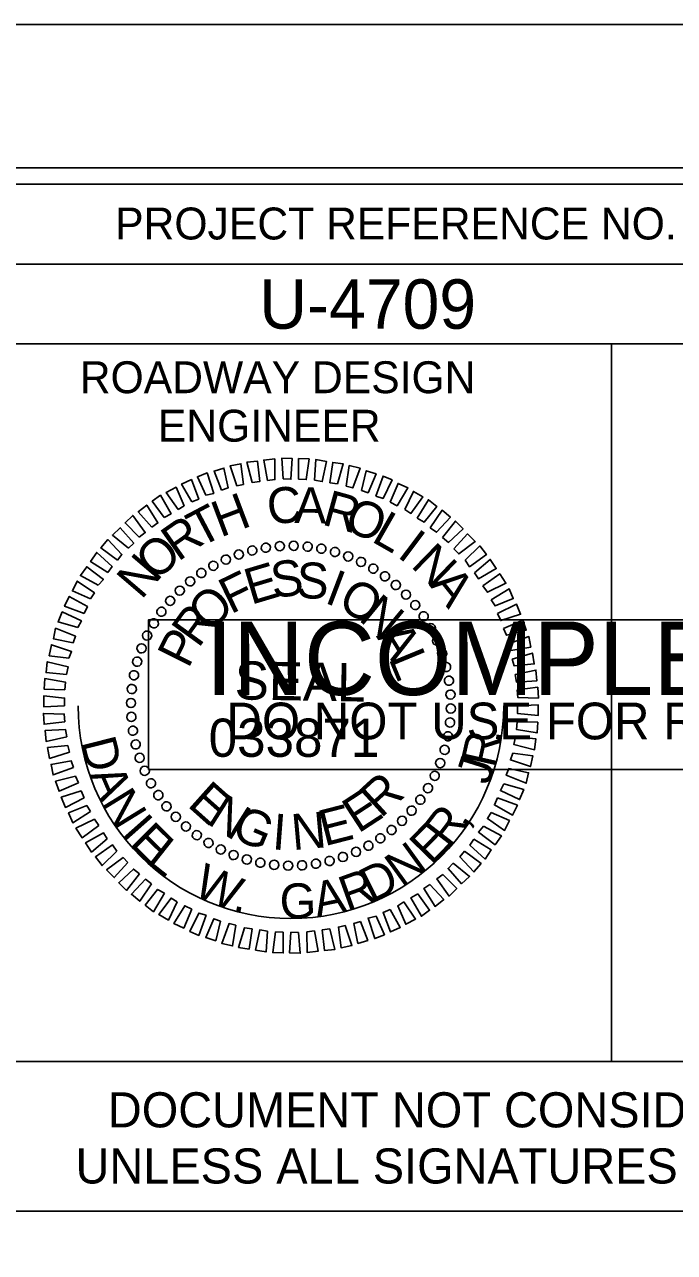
# Model space of a CAD drawing. Extents: x 1779926 to 1781626, y 618464 to 619564.
# Drawn here: x 1781400.9 to 1781502.8, y 619371.7 to 619564.2 of the extents above; entities that cross this region are included whole.
import ezdxf

# ---------------------------------------------------------------- set-up
doc = ezdxf.new("R2010")
doc.units = 0
for name, color, linetype in [('Old_Level_58', 7, 'Continuous'), ('Scratch_Level_0', 7, 'Continuous'), ('Sheet Data Field CELL', 7, 'Continuous'), ('Sheet Plot Border Inside CELL', 7, 'Continuous'), ('Sheet Plot Border Outside CELL', 7, 'Continuous'), ('Sheet Professional Seal CELL', 7, 'Continuous'), ('Sheet Profile CELL', 7, 'Continuous'), ('Sheet Profile Grid Major CELL', 7, 'Continuous'), ('Sheet Profile Grid Minor CELL', 7, 'Continuous'), ('Sheet Sticker Exception Certification CELL', 7, 'Continuous'), ('Sheet Sticker Incomplete CELL', 7, 'Continuous')]:
    doc.layers.add(name, color=color, linetype=linetype)

msp = doc.modelspace()

# ---------------------------------------------------------------- linework, layer by layer
at = {"layer": 'Old_Level_58'}
msp.add_lwpolyline([(1781392.9, 619378.14), (1781592.95, 619378.14), (1781592.95, 619314.19), (1781392.9, 619314.19)], close=True, dxfattribs=at)
at = {"layer": 'Scratch_Level_0'}
msp.add_arc((1781442.68, 619457.4), 33.36, 180, 360, dxfattribs=at)
at = {"layer": 'Sheet Plot Border Inside CELL'}
msp.add_lwpolyline([(1779938.96, 618486.64), (1781605.46, 618486.64), (1781605.46, 619541.74), (1779938.96, 619541.74)], close=True, dxfattribs=at)
at = {"layer": 'Sheet Plot Border Outside CELL'}
msp.add_lwpolyline([(1779925.96, 618464.19), (1781625.96, 618464.19), (1781625.96, 619564.19), (1779925.96, 619564.19)], close=True, dxfattribs=at)
at = {"layer": 'Sheet Professional Seal CELL'}
for p, q in [((1781440.93, 619482.45), (1781440.93, 619482.45)), ((1781443.13, 619482.5), (1781443.13, 619482.5)), ((1781445.33, 619482.35), (1781445.33, 619482.35)), ((1781434.48, 619481.15), (1781434.48, 619481.15)), ((1781436.58, 619481.75), (1781436.58, 619481.75)), ((1781438.78, 619482.15), (1781438.78, 619482.15)), ((1781447.48, 619482), (1781447.48, 619482)), ((1781449.58, 619481.55), (1781449.58, 619481.55)), ((1781451.68, 619480.85), (1781451.68, 619480.85)), ((1781430.53, 619479.35), (1781430.53, 619479.35)), ((1781432.48, 619480.35), (1781432.48, 619480.35)), ((1781453.68, 619479.95), (1781453.68, 619479.95)), ((1781455.63, 619478.95), (1781455.63, 619478.95)), ((1781426.88, 619476.95), (1781426.88, 619476.95)), ((1781428.63, 619478.2), (1781428.63, 619478.2)), ((1781457.43, 619477.7), (1781457.43, 619477.7)), ((1781425.23, 619475.45), (1781425.23, 619475.45)), ((1781459.18, 619476.35), (1781459.18, 619476.35)), ((1781460.73, 619474.85), (1781460.73, 619474.85)), ((1781423.73, 619473.9), (1781423.73, 619473.9)), ((1781462.23, 619473.2), (1781462.23, 619473.2)), ((1781422.38, 619472.15), (1781422.38, 619472.15)), ((1781463.48, 619471.45), (1781463.48, 619471.45)), ((1781421.13, 619470.35), (1781421.13, 619470.35)), ((1781464.63, 619469.55), (1781464.63, 619469.55)), ((1781420.13, 619468.4), (1781420.13, 619468.4)), ((1781465.63, 619467.6), (1781465.63, 619467.6)), ((1781419.23, 619466.4), (1781419.23, 619466.4)), ((1781466.43, 619465.6), (1781466.43, 619465.6)), ((1781418.53, 619464.3), (1781418.53, 619464.3)), ((1781467.03, 619463.5), (1781467.03, 619463.5)), ((1781418.08, 619462.2), (1781418.08, 619462.2)), ((1781467.43, 619461.3), (1781467.43, 619461.3)), ((1781417.73, 619460.05), (1781417.73, 619460.05)), ((1781417.58, 619457.85), (1781417.58, 619457.85)), ((1781442.68, 619457.4), (1781442.68, 619457.4)), ((1781467.73, 619459.15), (1781467.73, 619459.15)), ((1781417.63, 619455.65), (1781417.63, 619455.65)), ((1781467.78, 619456.95), (1781467.78, 619456.95)), ((1781417.93, 619453.5), (1781417.93, 619453.5)), ((1781467.63, 619454.75), (1781467.63, 619454.75)), ((1781467.28, 619452.6), (1781467.28, 619452.6)), ((1781418.33, 619451.3), (1781418.33, 619451.3)), ((1781466.83, 619450.5), (1781466.83, 619450.5)), ((1781418.93, 619449.2), (1781418.93, 619449.2)), ((1781466.13, 619448.4), (1781466.13, 619448.4)), ((1781419.73, 619447.2), (1781419.73, 619447.2)), ((1781465.23, 619446.4), (1781465.23, 619446.4)), ((1781420.73, 619445.25), (1781420.73, 619445.25)), ((1781464.23, 619444.45), (1781464.23, 619444.45)), ((1781421.88, 619443.35), (1781421.88, 619443.35)), ((1781462.98, 619442.65), (1781462.98, 619442.65)), ((1781423.13, 619441.6), (1781423.13, 619441.6)), ((1781461.63, 619440.9), (1781461.63, 619440.9)), ((1781424.63, 619439.95), (1781424.63, 619439.95)), ((1781426.18, 619438.45), (1781426.18, 619438.45)), ((1781460.13, 619439.35), (1781460.13, 619439.35)), ((1781427.93, 619437.1), (1781427.93, 619437.1)), ((1781456.73, 619436.6), (1781456.73, 619436.6)), ((1781458.48, 619437.85), (1781458.48, 619437.85)), ((1781429.73, 619435.85), (1781429.73, 619435.85)), ((1781431.68, 619434.85), (1781431.68, 619434.85)), ((1781452.88, 619434.45), (1781452.88, 619434.45)), ((1781454.83, 619435.45), (1781454.83, 619435.45)), ((1781433.68, 619433.95), (1781433.68, 619433.95)), ((1781435.78, 619433.25), (1781435.78, 619433.25)), ((1781437.88, 619432.8), (1781437.88, 619432.8)), ((1781440.03, 619432.45), (1781440.03, 619432.45)), ((1781442.23, 619432.3), (1781442.23, 619432.3)), ((1781444.43, 619432.35), (1781444.43, 619432.35)), ((1781446.58, 619432.65), (1781446.58, 619432.65)), ((1781448.78, 619433.05), (1781448.78, 619433.05)), ((1781450.88, 619433.65), (1781450.88, 619433.65))]:
    msp.add_line(p, q, dxfattribs=at)
for points in [[(1781438.98, 619492.7), (1781438.43, 619495.9), (1781440.13, 619496.1), (1781440.18, 619492.85)], [(1781441.48, 619492.95), (1781441.23, 619496.2), (1781442.88, 619496.15), (1781442.68, 619492.9)], [(1781443.88, 619492.9), (1781443.88, 619496.15), (1781445.53, 619496.1), (1781445.08, 619492.85)], [(1781446.38, 619492.75), (1781446.58, 619496), (1781448.23, 619495.7), (1781447.58, 619492.55)], [(1781429.33, 619490.4), (1781428.03, 619493.3), (1781429.53, 619493.9), (1781430.58, 619490.7)], [(1781431.78, 619491.2), (1781430.63, 619494.2), (1781432.18, 619494.65), (1781432.83, 619491.55)], [(1781434.18, 619491.85), (1781433.13, 619495), (1781434.83, 619495.35), (1781435.23, 619492.1)], [(1781436.58, 619492.4), (1781435.78, 619495.6), (1781437.43, 619495.75), (1781437.78, 619492.55)], [(1781448.78, 619492.35), (1781449.23, 619495.55), (1781450.88, 619495.3), (1781449.98, 619492.2)], [(1781451.33, 619491.8), (1781451.83, 619495.05), (1781453.53, 619494.65), (1781452.38, 619491.55)], [(1781453.73, 619491.15), (1781454.48, 619494.25), (1781456.03, 619493.75), (1781454.78, 619490.8)], [(1781427.13, 619489.35), (1781425.53, 619492.15), (1781427.08, 619492.85), (1781428.23, 619489.8)], [(1781455.98, 619490.25), (1781457.13, 619493.4), (1781458.53, 619492.8), (1781457.13, 619489.9)], [(1781458.23, 619489.3), (1781459.48, 619492.25), (1781461.03, 619491.55), (1781459.33, 619488.75)], [(1781422.78, 619486.9), (1781420.93, 619489.45), (1781422.23, 619490.4), (1781423.88, 619487.5)], [(1781424.98, 619488.15), (1781423.13, 619490.85), (1781424.68, 619491.65), (1781425.93, 619488.75)], [(1781460.53, 619488.15), (1781461.88, 619491), (1781463.38, 619490.15), (1781461.48, 619487.55)], [(1781420.88, 619485.4), (1781418.73, 619487.8), (1781420.08, 619488.85), (1781421.83, 619486.05)], [(1781462.48, 619486.8), (1781464.23, 619489.7), (1781465.53, 619488.65), (1781463.58, 619486.2)], [(1781418.88, 619483.85), (1781416.68, 619486.05), (1781417.88, 619487.25), (1781419.83, 619484.55)], [(1781464.53, 619485.3), (1781466.38, 619488.05), (1781467.68, 619486.95), (1781465.48, 619484.6)], [(1781466.43, 619483.75), (1781468.48, 619486.35), (1781469.68, 619485.15), (1781467.38, 619483)], [(1781417.23, 619482.1), (1781414.68, 619484.15), (1781415.93, 619485.3), (1781418.03, 619482.9)], [(1781468.23, 619482), (1781470.38, 619484.35), (1781471.58, 619483.15), (1781468.98, 619481.2)], [(1781415.48, 619480.2), (1781412.88, 619482.15), (1781413.98, 619483.45), (1781416.18, 619481.1)], [(1781469.98, 619480.2), (1781472.28, 619482.45), (1781473.33, 619481.1), (1781470.68, 619479.2)], [(1781413.98, 619478.3), (1781411.28, 619480), (1781412.23, 619481.45), (1781414.63, 619479.25)], [(1781412.48, 619476.3), (1781409.68, 619477.8), (1781410.68, 619479.2), (1781413.28, 619477.2)], [(1781471.48, 619478.25), (1781473.93, 619480.35), (1781474.88, 619478.9), (1781472.08, 619477.3)], [(1781411.28, 619474.15), (1781408.43, 619475.4), (1781409.18, 619476.95), (1781411.88, 619475.1)], [(1781472.78, 619476.2), (1781475.43, 619478.1), (1781476.38, 619476.6), (1781473.48, 619475.2)], [(1781474.08, 619474), (1781476.88, 619475.75), (1781477.53, 619474.2), (1781474.68, 619473.05)], [(1781410.28, 619471.85), (1781407.18, 619473), (1781407.93, 619474.55), (1781410.78, 619472.95)], [(1781475.08, 619471.85), (1781478.03, 619473.35), (1781478.68, 619471.75), (1781475.58, 619470.75)], [(1781409.28, 619469.65), (1781406.18, 619470.55), (1781406.83, 619472.1), (1781409.83, 619470.7)], [(1781475.98, 619469.5), (1781479.03, 619470.8), (1781479.58, 619469.25), (1781476.48, 619468.45)], [(1781408.53, 619467.25), (1781405.43, 619467.9), (1781405.78, 619469.55), (1781408.93, 619468.3)], [(1781407.88, 619464.85), (1781404.78, 619465.25), (1781405.13, 619466.95), (1781408.28, 619465.9)], [(1781476.78, 619467.1), (1781479.98, 619468.25), (1781480.28, 619466.6), (1781477.13, 619466.05)], [(1781477.38, 619464.7), (1781480.53, 619465.65), (1781480.83, 619463.95), (1781477.68, 619463.65)], [(1781407.48, 619462.3), (1781404.28, 619462.6), (1781404.48, 619464.3), (1781407.73, 619463.5)], [(1781407.23, 619459.9), (1781403.98, 619460), (1781404.08, 619461.65), (1781407.33, 619461.1)], [(1781477.83, 619462.3), (1781481.08, 619463), (1781481.23, 619461.3), (1781478.03, 619461.1)], [(1781478.13, 619459.9), (1781481.38, 619460.3), (1781481.48, 619458.6), (1781478.23, 619458.7)], [(1781407.18, 619457.4), (1781403.93, 619457.25), (1781403.93, 619458.95), (1781407.18, 619458.6)], [(1781478.18, 619457.4), (1781481.43, 619457.55), (1781481.43, 619455.85), (1781478.18, 619456.2)], [(1781407.23, 619454.9), (1781403.98, 619454.5), (1781403.88, 619456.2), (1781407.13, 619456.1)], [(1781407.53, 619452.5), (1781404.28, 619451.8), (1781404.13, 619453.5), (1781407.33, 619453.7)], [(1781478.13, 619454.9), (1781481.38, 619454.8), (1781481.28, 619453.15), (1781478.03, 619453.7)], [(1781477.88, 619452.5), (1781481.08, 619452.2), (1781480.88, 619450.5), (1781477.63, 619451.3)], [(1781407.98, 619450.1), (1781404.83, 619449.15), (1781404.53, 619450.85), (1781407.68, 619451.15)], [(1781477.48, 619449.95), (1781480.58, 619449.55), (1781480.23, 619447.85), (1781477.08, 619448.9)], [(1781408.58, 619447.7), (1781405.38, 619446.55), (1781405.08, 619448.2), (1781408.23, 619448.75)], [(1781409.38, 619445.3), (1781406.33, 619444), (1781405.78, 619445.55), (1781408.88, 619446.35)], [(1781476.83, 619447.55), (1781479.93, 619446.9), (1781479.58, 619445.25), (1781476.43, 619446.5)], [(1781410.28, 619442.95), (1781407.33, 619441.45), (1781406.68, 619443.05), (1781409.78, 619444.05)], [(1781476.08, 619445.15), (1781479.18, 619444.25), (1781478.53, 619442.7), (1781475.53, 619444.1)], [(1781475.08, 619442.95), (1781478.18, 619441.8), (1781477.43, 619440.25), (1781474.58, 619441.85)], [(1781411.28, 619440.8), (1781408.48, 619439.05), (1781407.83, 619440.6), (1781410.68, 619441.75)], [(1781474.08, 619440.65), (1781476.93, 619439.4), (1781476.18, 619437.85), (1781473.48, 619439.7)], [(1781412.58, 619438.6), (1781409.93, 619436.7), (1781408.98, 619438.2), (1781411.88, 619439.6)], [(1781472.88, 619438.5), (1781475.68, 619437), (1781474.68, 619435.6), (1781472.08, 619437.6)], [(1781413.88, 619436.55), (1781411.43, 619434.45), (1781410.48, 619435.9), (1781413.28, 619437.5)], [(1781471.38, 619436.5), (1781474.08, 619434.8), (1781473.13, 619433.35), (1781470.73, 619435.55)], [(1781415.38, 619434.6), (1781413.08, 619432.35), (1781412.03, 619433.7), (1781414.68, 619435.6)], [(1781469.88, 619434.6), (1781472.48, 619432.65), (1781471.38, 619431.35), (1781469.18, 619433.7)], [(1781417.13, 619432.8), (1781414.98, 619430.45), (1781413.78, 619431.65), (1781416.38, 619433.6)], [(1781468.13, 619432.7), (1781470.68, 619430.65), (1781469.43, 619429.5), (1781467.33, 619431.9)], [(1781418.93, 619431.05), (1781416.88, 619428.45), (1781415.68, 619429.65), (1781417.98, 619431.8)], [(1781466.48, 619430.95), (1781468.68, 619428.75), (1781467.48, 619427.55), (1781465.53, 619430.25)], [(1781420.83, 619429.5), (1781418.98, 619426.75), (1781417.68, 619427.85), (1781419.88, 619430.2)], [(1781422.88, 619428), (1781421.13, 619425.1), (1781419.83, 619426.15), (1781421.78, 619428.6)], [(1781464.48, 619429.4), (1781466.63, 619427), (1781465.28, 619425.95), (1781463.53, 619428.75)], [(1781424.83, 619426.65), (1781423.48, 619423.8), (1781421.98, 619424.65), (1781423.88, 619427.25)], [(1781460.38, 619426.65), (1781462.23, 619423.95), (1781460.68, 619423.15), (1781459.43, 619426.05)], [(1781462.58, 619427.9), (1781464.43, 619425.35), (1781463.13, 619424.4), (1781461.48, 619427.3)], [(1781427.13, 619425.5), (1781425.88, 619422.55), (1781424.33, 619423.25), (1781426.03, 619426.05)], [(1781429.38, 619424.55), (1781428.23, 619421.4), (1781426.83, 619422), (1781428.23, 619424.9)], [(1781458.23, 619425.45), (1781459.83, 619422.65), (1781458.28, 619421.95), (1781457.13, 619425)], [(1781431.63, 619423.65), (1781430.88, 619420.55), (1781429.33, 619421.05), (1781430.58, 619424)], [(1781434.03, 619423), (1781433.53, 619419.75), (1781431.83, 619420.15), (1781432.98, 619423.25)], [(1781451.18, 619422.95), (1781452.23, 619419.8), (1781450.53, 619419.45), (1781450.13, 619422.7)], [(1781453.58, 619423.6), (1781454.73, 619420.6), (1781453.18, 619420.15), (1781452.53, 619423.25)], [(1781456.03, 619424.4), (1781457.33, 619421.5), (1781455.83, 619420.9), (1781454.78, 619424.1)], [(1781436.58, 619422.45), (1781436.13, 619419.25), (1781434.48, 619419.5), (1781435.38, 619422.6)], [(1781438.98, 619422.05), (1781438.78, 619418.8), (1781437.13, 619419.1), (1781437.78, 619422.25)], [(1781441.48, 619421.9), (1781441.48, 619418.65), (1781439.83, 619418.7), (1781440.28, 619421.95)], [(1781443.88, 619421.85), (1781444.13, 619418.6), (1781442.48, 619418.65), (1781442.68, 619421.9)], [(1781446.38, 619422.1), (1781446.93, 619418.9), (1781445.23, 619418.7), (1781445.18, 619421.95)], [(1781448.78, 619422.4), (1781449.58, 619419.2), (1781447.93, 619419.05), (1781447.58, 619422.25)]]:
    msp.add_lwpolyline(points, close=True, dxfattribs=at)
for centre, major_axis in [((1781436.61, 619481.74), (-0.174, 0.699)), ((1781438.75, 619482.17), (-0.113, 0.711)), ((1781440.93, 619482.42), (-0.05, 0.718)), ((1781443.11, 619482.48), (0.013, 0.72)), ((1781445.3, 619482.34), (0.075, 0.716)), ((1781447.46, 619482.02), (0.137, 0.707)), ((1781432.47, 619480.31), (-0.293, 0.658)), ((1781434.51, 619481.11), (-0.234, 0.681)), ((1781449.59, 619481.51), (0.198, 0.692)), ((1781451.66, 619480.81), (0.258, 0.672)), ((1781453.67, 619479.94), (0.316, 0.647)), ((1781428.65, 619478.19), (-0.403, 0.597)), ((1781430.52, 619479.34), (-0.349, 0.63)), ((1781455.59, 619478.9), (0.371, 0.617)), ((1781457.42, 619477.69), (0.423, 0.582)), ((1781426.89, 619476.89), (-0.453, 0.56)), ((1781459.13, 619476.33), (0.472, 0.543)), ((1781423.75, 619473.85), (-0.543, 0.472)), ((1781425.25, 619475.44), (-0.5, 0.518)), ((1781460.72, 619474.82), (0.518, 0.5)), ((1781422.38, 619472.14), (-0.582, 0.423)), ((1781462.17, 619473.18), (0.56, 0.453)), ((1781421.18, 619470.32), (-0.617, 0.371)), ((1781463.47, 619471.42), (0.597, 0.403)), ((1781420.13, 619468.39), (-0.647, 0.316)), ((1781464.61, 619469.56), (0.63, 0.349)), ((1781419.26, 619466.39), (-0.672, 0.258)), ((1781465.59, 619467.6), (0.658, 0.293)), ((1781418.57, 619464.31), (-0.692, 0.198)), ((1781466.39, 619465.57), (0.681, 0.234)), ((1781467.01, 619463.47), (0.699, 0.174)), ((1781418.06, 619462.19), (-0.707, 0.137)), ((1781467.45, 619461.32), (0.711, 0.113)), ((1781417.73, 619460.02), (-0.716, 0.075)), ((1781467.69, 619459.15), (0.718, 0.05)), ((1781417.6, 619457.84), (-0.72, 0.013)), ((1781467.75, 619456.96), (0.72, -0.013)), ((1781417.66, 619455.65), (-0.718, -0.05)), ((1781467.62, 619454.78), (0.716, -0.075)), ((1781417.9, 619453.48), (-0.711, -0.113)), ((1781418.34, 619451.33), (-0.699, -0.174)), ((1781467.29, 619452.61), (0.707, -0.137)), ((1781418.96, 619449.24), (-0.681, -0.234)), ((1781466.78, 619450.49), (0.692, -0.198)), ((1781419.76, 619447.2), (-0.658, -0.293)), ((1781466.09, 619448.41), (0.672, -0.258)), ((1781420.74, 619445.24), (-0.63, -0.349)), ((1781465.22, 619446.41), (0.647, -0.316)), ((1781421.88, 619443.38), (-0.597, -0.403)), ((1781464.17, 619444.48), (0.617, -0.371)), ((1781423.18, 619441.62), (-0.56, -0.453)), ((1781462.97, 619442.66), (0.582, -0.423)), ((1781424.63, 619439.98), (-0.518, -0.5)), ((1781460.1, 619439.36), (0.5, -0.518)), ((1781461.6, 619440.95), (0.543, -0.472)), ((1781426.22, 619438.47), (-0.472, -0.543)), ((1781458.46, 619437.91), (0.453, -0.56)), ((1781427.93, 619437.11), (-0.423, -0.582)), ((1781429.76, 619435.9), (-0.371, -0.617)), ((1781454.83, 619435.46), (0.349, -0.63)), ((1781456.7, 619436.61), (0.403, -0.597)), ((1781431.68, 619434.86), (-0.316, -0.647)), ((1781433.69, 619433.99), (-0.258, -0.672)), ((1781450.84, 619433.69), (0.234, -0.681)), ((1781452.88, 619434.49), (0.293, -0.658)), ((1781435.76, 619433.29), (-0.198, -0.692)), ((1781437.89, 619432.78), (-0.137, -0.707)), ((1781440.05, 619432.46), (-0.075, -0.716)), ((1781442.24, 619432.32), (-0.013, -0.72)), ((1781444.42, 619432.38), (0.05, -0.718)), ((1781446.6, 619432.63), (0.113, -0.711)), ((1781448.74, 619433.07), (0.174, -0.699))]:
    msp.add_ellipse(centre, major_axis=major_axis, ratio=0.999708, dxfattribs=at)
at = {"layer": 'Sheet Profile CELL'}
for p, q in [((1781392.91, 619526.64), (1781592.96, 619526.64)), ((1781492.96, 619514.14), (1781492.96, 619401.69))]:
    msp.add_line(p, q, dxfattribs=at)
for points in [[(1781592.96, 619539.19), (1780092.96, 619539.19), (1780092.96, 618489.19), (1781592.96, 618489.19)], [(1781392.91, 619539.19), (1781592.96, 619539.19), (1781592.96, 619514.14), (1781392.91, 619514.14)], [(1781392.91, 619514.14), (1781492.96, 619514.14), (1781492.96, 619401.64), (1781392.91, 619401.64)], [(1781492.96, 619514.14), (1781592.96, 619514.14), (1781592.96, 619401.64), (1781492.96, 619401.64)]]:
    msp.add_lwpolyline(points, close=True, dxfattribs=at)
at = {"layer": 'Sheet Profile Grid Major CELL'}
msp.add_lwpolyline([(1780842.96, 619039.19), (1780892.96, 619039.19), (1780892.96, 619539.19), (1780942.96, 619539.19), (1780942.96, 619039.19), (1780992.96, 619039.19), (1780992.96, 619539.19), (1781042.96, 619539.19), (1781042.96, 619039.19), (1781092.96, 619039.19), (1781092.96, 619539.19), (1781142.96, 619539.19), (1781142.96, 619039.19), (1781192.96, 619039.19), (1781192.96, 619539.19), (1781242.96, 619539.19), (1781242.96, 619039.19), (1781292.96, 619039.19), (1781292.96, 619539.19), (1781342.96, 619539.19), (1781342.96, 619039.19), (1781392.96, 619039.19), (1781392.96, 619539.19), (1781419.26, 619539.19)], dxfattribs=at)
at = {"layer": 'Sheet Sticker Exception Certification CELL'}
for p, q in [((1781392.91, 619401.64), (1781592.95, 619401.64)), ((1781392.91, 619401.64), (1781592.95, 619401.64)), ((1781592.95, 619378.14), (1781392.91, 619378.14)), ((1781592.95, 619378.14), (1781392.91, 619378.14))]:
    msp.add_line(p, q, dxfattribs=at)
at = {"layer": 'Sheet Sticker Incomplete CELL'}
msp.add_lwpolyline([(1781420.37, 619447.38), (1781420.37, 619470.88), (1781567.37, 619470.88), (1781567.37, 619447.38)], close=True, dxfattribs=at)

# ---------------------------------------------------------------- texts
at = {"layer": 'Sheet Data Field CELL'}
msp.add_text('U-4709', height=7.75, dxfattribs=at).set_placement((1781437.72, 619516.5))
at = {"layer": 'Sheet Professional Seal CELL'}
for s, height, rotation, p in [('H', 5.64, 20.6195, (1781431.63, 619483.75)), ('C', 5.64, 6.2199, (1781439.23, 619485.75)), ('A', 5.64, 359.0203, (1781443.18, 619486.05)), ('R', 5.64, 344.6211, (1781447.38, 619485.85)), ('T', 5.64, 27.8198, (1781428.38, 619482.1)), ('O', 5.64, 337.4212, (1781450.73, 619485.1)), ('R', 5.64, 35.0205, (1781424.98, 619479.9)), ('L', 5.64, 330.2209, (1781455.13, 619483.25)), ('I', 5.64, 323.0201, (1781459.18, 619480.85)), ('O', 5.64, 42.2217, (1781421.53, 619476.8)), ('N', 5.64, 315.8189, (1781461.33, 619479.3)), ('N', 5.64, 49.4235, (1781419.23, 619473.9)), ('F', 5.64, 25.967, (1781433.23, 619471.7)), ('E', 5.64, 16.6111, (1781436.43, 619473.2)), ('S', 5.64, 7.2556, (1781439.88, 619474.25)), ('S', 5.64, 357.9004, (1781443.48, 619474.3)), ('I', 5.64, 339.1896, (1781447.78, 619473.6)), ('O', 5.64, 329.8335, (1781449.78, 619472.9)), ('A', 5.64, 308.6172, (1781464.28, 619476.35)), ('O', 5.64, 44.6812, (1781429.93, 619468.75)), ('N', 5.64, 320.4766, (1781453.13, 619470.9)), ('R', 5.64, 54.0397, (1781428.18, 619466.3)), ('P', 5.64, 63.3989, (1781426.58, 619463.1)), ('A', 5.64, 301.7603, (1781455.98, 619468.3)), ('L', 5.64, 292.4008, (1781457.93, 619464.85)), ('SEAL', 5.998, 359, (1781433.83, 619458.4)), ('R', 5.64, 42.4814, (1781456.78, 619439.65)), ('E', 5.64, 318.2769, (1781426.28, 619441.75)), ('E', 5.64, 33.1241, (1781453.23, 619437.3)), ('N', 5.64, 327.634, (1781429.28, 619439.05)), ('E', 5.64, 14.4118, (1781447.93, 619435.35)), ('G', 5.64, 336.9902, (1781433.08, 619436.8)), ('I', 5.64, 355.7012, (1781439.63, 619434.9)), ('N', 5.64, 5.0564, (1781442.98, 619434.75))]:
    msp.add_text(s, height=height, rotation=rotation, dxfattribs=at).set_placement(p)
at = {"layer": 'Sheet Profile CELL'}
for s, height, p in [('PROJECT REFERENCE NO.', 5.0001, (1781415.12, 619530.5)), ('ROADWAY DESIGN', 5.0001, (1781409.57, 619506.4)), ('ENGINEER', 5, (1781421.82, 619498.8))]:
    msp.add_text(s, height=height, dxfattribs=at).set_placement(p)
at = {"layer": 'Sheet Profile Grid Minor CELL'}
msp.add_text('033871', height=5.998, dxfattribs=at).set_placement((1781429.78, 619449.39))
for s, rotation, p in [('D', 284.2682, (1781409.68, 619451.76)), ('R', 77.3541, (1781474.65, 619447.5)), ('.', 84.2805, (1781475.61, 619451.43)), ('J', 72.4855, (1781473.69, 619444.82)), ('A', 293.4128, (1781411, 619446.59)), ('N', 301.5986, (1781412.86, 619442.19)), ('I', 311.5304, (1781415.93, 619437.27)), ('R', 52.3788, (1781467.48, 619434.92)), ('E', 315.0508, (1781417.22, 619435.67)), ('E', 45.7958, (1781464.74, 619432.23)), (',', 59.3052, (1781470.01, 619438.08)), ('L', 321.6338, (1781419.88, 619432.89)), ('N', 35.8641, (1781460.06, 619428.8)), ('W', 336.8891, (1781427.13, 619427.76)), ('D', 26.7195, (1781455.3, 619426.4)), ('R', 19.793, (1781451.47, 619425.11)), ('G', 1.6755, (1781440.99, 619423.97)), ('A', 11.6072, (1781446.78, 619424.18)), ('.', 348.4952, (1781433.41, 619425.24))]:
    msp.add_text(s, height=5.5, rotation=rotation, dxfattribs=at).set_placement(p)
at = {"layer": 'Sheet Sticker Exception Certification CELL'}
for s, p in [('DOCUMENT NOT CONSIDERED FINAL', (1781413.98, 619391.3)), ('DOCUMENT NOT CONSIDERED FINAL', (1781413.98, 619391.3)), ('UNLESS ALL SIGNATURES COMPLETED', (1781408.91, 619382.5)), ('UNLESS ALL SIGNATURES COMPLETED', (1781408.91, 619382.5))]:
    msp.add_text(s, height=5.5, dxfattribs=at).set_placement(p)
at = {"layer": 'Sheet Sticker Incomplete CELL'}
for s, height, p in [('INCOMPLETE PLANS', 11.52, (1781429.32, 619459.08)), ('DO NOT USE FOR R/W ACQUISITION', 5.76, (1781432.57, 619452.13))]:
    msp.add_text(s, height=height, dxfattribs=at).set_placement(p)

doc.saveas('drawing.dxf')
